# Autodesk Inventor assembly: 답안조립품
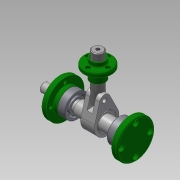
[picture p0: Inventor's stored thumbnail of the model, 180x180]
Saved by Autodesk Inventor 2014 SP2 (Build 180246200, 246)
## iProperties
Created: 2016-08
Part Number: 답안조립품
Document SubType Name: Assembly
Designer: user
Author: user
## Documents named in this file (10)
- C:\Users\user\Desktop\460820V1015\답안조립품.iam
- C:\Users\user\Desktop\460820V1015\본체.ipt
- C:\Users\user\Desktop\460820V1015\뒤커버.ipt
- C:\Users\user\Desktop\460820V1015\앞커버.ipt
- C:\Users\user\Desktop\460820V1015\베어링 15 x 35 x 11.ipt
- C:\Users\user\Desktop\460820V1015\상부부시.ipt
- C:\Users\user\Desktop\460820V1015\멈춤링 15 x 1.ipt
- C:\Users\user\Desktop\460820V1015\편심축.ipt
- C:\Users\user\Desktop\460820V1015\링크.ipt
- C:\Users\user\Desktop\460820V1015\슬라이드바.ipt
